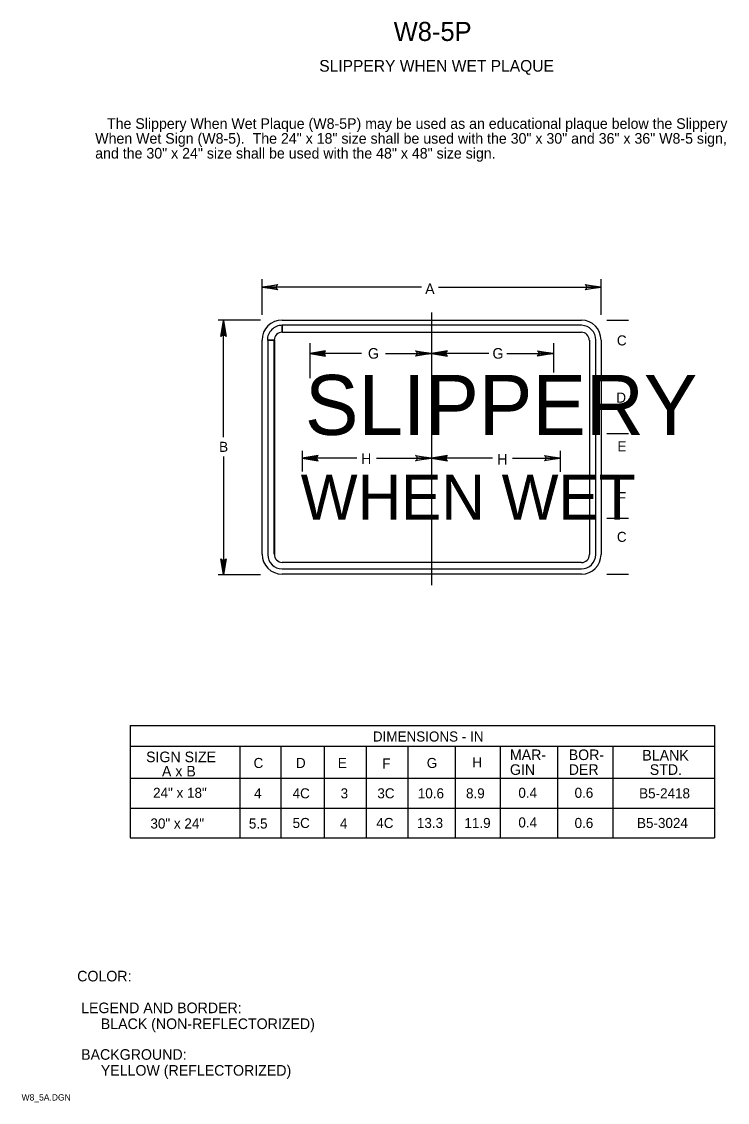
# Model space of a CAD drawing. Extents: x 0.012 to 0.179, y 0.004 to 0.259.
import ezdxf

# ---------------------------------------------------------------- set-up
doc = ezdxf.new("R2010")
doc.units = 0
for name, color, linetype in [('1', 7, 'Continuous'), ('12', 7, 'Continuous'), ('2', 7, 'Continuous'), ('3', 7, 'Continuous')]:
    doc.layers.add(name, color=color, linetype=linetype)

# ---------------------------------------------------------------- blocks, each defined once
blk = doc.blocks.new('RARROW')
at = {"layer": '3'}
for p, q in [((-2.156, 0.28500000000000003), (-2.2665, 0.384625)), ((-2.2665, 0.384625), (0, 0)), ((0, 0), (-2.2665, -0.379125)), ((-2.156, 0.28500000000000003), (-2.075625, 0.12075)), ((0, 0), (-2.156, 0.28500000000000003)), ((-2.14975, -0.2705), (0, 0)), ((-2.075625, 0.12075), (0, 0)), ((0, 0), (-2.074, -0.108)), ((-2.2665, -0.379125), (-2.14975, -0.2705)), ((-2.074, -0.108), (-2.14975, -0.2705))]:
    blk.add_line(p, q, dxfattribs=at)

msp = doc.modelspace()

# ---------------------------------------------------------------- linework, layer by layer
at = {"layer": '3'}
for p, q in [((0.069125, 0.18987500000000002), (0.069125, 0.19825)), ((0.149125, 0.18987500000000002), (0.149125, 0.19825)), ((0.10675, 0.196375), (0.069125, 0.196375)), ((0.11075, 0.196375), (0.149125, 0.196375)), ((0.109125, 0.19037500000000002), (0.109125, 0.126)), ((0.06875, 0.18862500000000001), (0.058750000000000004, 0.18862500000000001)), ((0.06, 0.161), (0.06, 0.18862500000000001)), ((0.073875, 0.18862500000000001), (0.1445, 0.18862500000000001)), ((0.1445, 0.187375), (0.073875, 0.187375)), ((0.073875, 0.187375), (0.07387569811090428, 0.18574738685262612)), ((0.07387569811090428, 0.18574738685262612), (0.073875, 0.187375)), ((0.1505, 0.18862500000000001), (0.155625, 0.18862500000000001)), ((0.069125, 0.133375), (0.069125, 0.183875)), ((0.07037500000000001, 0.183875), (0.07201621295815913, 0.18388790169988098)), ((0.07200000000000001, 0.183875), (0.07044815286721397, 0.18388790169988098)), ((0.07050000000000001, 0.183875), (0.07050000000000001, 0.13325)), ((0.07200000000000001, 0.133375), (0.07200000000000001, 0.183875)), ((0.07200000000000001, 0.133375), (0.07200000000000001, 0.183875)), ((0.0720351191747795, 0.18384855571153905), (0.0720351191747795, 0.13334855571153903)), ((0.0720351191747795, 0.13334855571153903), (0.0720351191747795, 0.18384855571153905)), ((0.0720351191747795, 0.18384855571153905), (0.0720351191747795, 0.13334855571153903)), ((0.073875, 0.18575), (0.1445, 0.18575)), ((0.146375, 0.183875), (0.146375, 0.13325)), ((0.147875, 0.13325), (0.147875, 0.183875)), ((0.149125, 0.183875), (0.149125, 0.13325)), ((0.080375, 0.183125), (0.080375, 0.174875)), ((0.137875, 0.183125), (0.137875, 0.17625)), ((0.092625, 0.18075), (0.080375, 0.18075)), ((0.09825, 0.18075), (0.109125, 0.18075)), ((0.122625, 0.18075), (0.109125, 0.18075)), ((0.12687500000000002, 0.18075), (0.137875, 0.18075)), ((0.1505, 0.17525000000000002), (0.155625, 0.17525000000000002)), ((0.1505, 0.161875), (0.155625, 0.161875)), ((0.06, 0.15637500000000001), (0.06, 0.128625)), ((0.078625, 0.15775), (0.078625, 0.152875)), ((0.0915, 0.156), (0.078625, 0.156)), ((0.096125, 0.156), (0.109125, 0.156)), ((0.1235, 0.156), (0.109125, 0.156)), ((0.12825, 0.156), (0.1395, 0.156)), ((0.1395, 0.15775), (0.1395, 0.15275)), ((0.1505, 0.151875), (0.155625, 0.151875)), ((0.1505, 0.141875), (0.155625, 0.141875)), ((0.1445, 0.131375), (0.073875, 0.131375)), ((0.06875, 0.1285), (0.058750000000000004, 0.1285)), ((0.073875, 0.129875), (0.1445, 0.129875)), ((0.1445, 0.128625), (0.073875, 0.128625)), ((0.1505, 0.128625), (0.155625, 0.128625)), ((0.038, 0.092875), (0.175875, 0.092875)), ((0.038039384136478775, 0.09287569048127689), (0.038039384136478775, 0.0663756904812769)), ((0.17593791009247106, 0.09287569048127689), (0.17593791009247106, 0.0663756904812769)), ((0.038, 0.088), (0.175875, 0.088)), ((0.06387418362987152, 0.08802738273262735), (0.06387418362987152, 0.0663756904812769)), ((0.07353938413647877, 0.08800069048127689), (0.07353938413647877, 0.0663756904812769)), ((0.08375655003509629, 0.08800069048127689), (0.08375655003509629, 0.0663756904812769)), ((0.09368984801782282, 0.08800069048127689), (0.09368984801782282, 0.0663756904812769)), ((0.10356484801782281, 0.08800069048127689), (0.10356484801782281, 0.0663756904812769)), ((0.11468984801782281, 0.08800069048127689), (0.11468984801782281, 0.0663756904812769)), ((0.1253620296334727, 0.08802738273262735), (0.1253620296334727, 0.0663756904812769)), ((0.13882622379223, 0.08802738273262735), (0.13882622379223, 0.0663756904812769)), ((0.1519163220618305, 0.08802738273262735), (0.1519163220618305, 0.0663756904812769)), ((0.038, 0.0805), (0.175875, 0.0805)), ((0.038, 0.073375), (0.175875, 0.073375)), ((0.038, 0.066375), (0.175875, 0.066375))]:
    msp.add_line(p, q, dxfattribs=at)
for centre, radius, start, end in [((0.07387500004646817, 0.1838749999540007), 0.004750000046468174, 90, 180), ((0.07387499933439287, 0.18387500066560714), 0.003499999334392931, 89.9999888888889, 180.00001111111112), ((0.14443750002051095, 0.18393750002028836), 0.004687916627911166, 359.2361, 89.23610000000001), ((0.14443749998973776, 0.18393749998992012), 0.003438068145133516, 358.95837222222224, 88.95837222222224), ((0.07387569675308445, 0.1838879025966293), 0.0018594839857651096, 90, 180), ((0.1444956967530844, 0.1838879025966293), 0.0018594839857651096, 0, 90), ((0.07387499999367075, 0.13337499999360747), 0.004749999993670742, 180, 270), ((0.07387500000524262, 0.13325000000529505), 0.003375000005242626, 180, 270), ((0.07392547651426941, 0.13329877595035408), 0.001891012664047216, 178.49155000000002, 268.49155), ((0.14450000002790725, 0.13324999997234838), 0.004624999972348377, 270, 0), ((0.1444999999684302, 0.1332500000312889), 0.0033750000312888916, 270, 0), ((0.14449999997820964, 0.1332500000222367), 0.0018750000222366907, 270, 0)]:
    msp.add_arc(centre, radius, start, end, dxfattribs=at)

# ---------------------------------------------------------------- block references
at = {"layer": '3', "xscale": 0.0016545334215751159}
for p, yscale, rotation in [((0.069125, 0.196375), 0.0016366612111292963, 180), ((0.06, 0.1885), 0.0016366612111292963, 90), ((0.080375, 0.18075), -0.0016366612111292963, -180), ((0.109125, 0.18075), -0.0016366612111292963, -180), ((0.078625, 0.156), -0.0016366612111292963, -180), ((0.109125, 0.156), -0.0016366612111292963, -180), ((0.06, 0.1285), 0.0016366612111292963, -90)]:
    msp.add_blockref('RARROW', p, dxfattribs=dict(at, yscale=yscale, rotation=rotation))
at = {"layer": '3', "xscale": 0.0016545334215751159, "yscale": 0.0016366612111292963}
for p in [(0.149125, 0.196375), (0.109125, 0.18075), (0.137875, 0.18075), (0.109125, 0.156), (0.1395, 0.156)]:
    msp.add_blockref('RARROW', p, dxfattribs=at)

# ---------------------------------------------------------------- texts
at = {"layer": '1'}
for s, height, p in [('W8-5P', 0.0045000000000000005, (0.10019590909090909, 0.2545)), ('SLIPPERY WHEN WET PLAQUE', 0.00275025, (0.082625, 0.24725)), ('COLOR:', 0.0024997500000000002, (0.025500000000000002, 0.0325)), (' LEGEND AND BORDER:', 0.0024997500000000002, (0.025500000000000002, 0.025)), ('      BLACK (NON-REFLECTORIZED)', 0.0024997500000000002, (0.025500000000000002, 0.02125)), (' BACKGROUND:', 0.0024997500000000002, (0.025500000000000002, 0.014)), ('      YELLOW (REFLECTORIZED)', 0.0024997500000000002, (0.025500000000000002, 0.01025)), ('W8_5A.DGN', 0.0015, (0.012375, 0.004375))]:
    msp.add_text(s, height=height, dxfattribs=at).set_placement(p)
at = {"layer": '12'}
for s, height, p in [('SLIPPERY', 0.01416, (0.07925, 0.1615)), ('WHEN WET', 0.01064025, (0.07825, 0.14150000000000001))]:
    msp.add_text(s, height=height, dxfattribs=at).set_placement(p)
at = {"layer": '2'}
for s, p in [('   The Slippery When Wet Plaque (W8-5P) may be used as an educational plaque below the Slippery ', (0.029750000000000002, 0.233749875)), ('When Wet Sign (W8-5).  The 24" x 18" size shall be used with the 30" x 30" and 36" x 36" W8-5 sign, ', (0.029750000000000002, 0.230250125)), ('and the 30" x 24" size shall be used with the 48" x 48" size sign.', (0.029750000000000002, 0.226750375))]:
    msp.add_text(s, height=0.0024997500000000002, dxfattribs=at).set_placement(p)
at = {"layer": '3'}
for s, height, p in [('A', 0.0024997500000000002, (0.107625, 0.19475)), ('C', 0.0023752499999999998, (0.152875, 0.182625)), ('G', 0.0024997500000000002, (0.094125, 0.1795)), ('G', 0.0024997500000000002, (0.1235, 0.1795)), ('D', 0.0023752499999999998, (0.15275, 0.169125)), ('B', 0.0023752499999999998, (0.059000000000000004, 0.1575)), ('E', 0.0023752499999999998, (0.153, 0.15762500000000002)), ('H', 0.0024997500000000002, (0.0925, 0.154625)), ('H', 0.0024997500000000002, (0.124625, 0.1545)), ('F', 0.0024997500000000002, (0.153, 0.1455)), ('C', 0.0023752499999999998, (0.152875, 0.13625)), ('DIMENSIONS - IN', 0.0023752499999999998, (0.09527678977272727, 0.089125)), ('SIGN SIZE', 0.0024997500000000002, (0.04175, 0.08425)), ('MAR-', 0.0024997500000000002, (0.12762500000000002, 0.08475)), ('BOR-', 0.0024997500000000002, (0.14150000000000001, 0.08475)), ('BLANK', 0.0024997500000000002, (0.15887500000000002, 0.084625)), ('C', 0.0023752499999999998, (0.067125, 0.082875)), ('D', 0.0023752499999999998, (0.077125, 0.082875)), ('E', 0.0023752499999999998, (0.08700000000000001, 0.082875)), ('F', 0.0023752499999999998, (0.0975, 0.08275)), ('G', 0.0023752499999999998, (0.108, 0.082875)), ('H', 0.0023752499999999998, (0.11875000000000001, 0.083)), ('A x B', 0.0024997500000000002, (0.0455, 0.080875)), ('GIN', 0.0024997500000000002, (0.12762500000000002, 0.08125)), ('DER', 0.0024997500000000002, (0.14150000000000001, 0.08125)), ('STD.', 0.0024997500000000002, (0.160625, 0.08125)), ('24" x 18"', 0.0023752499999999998, (0.04340823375, 0.07583573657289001)), ('4', 0.0023752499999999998, (0.06724652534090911, 0.07571073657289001)), ('4C', 0.0023752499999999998, (0.07633985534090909, 0.07571073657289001)), ('3', 0.0023752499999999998, (0.08766759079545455, 0.07571073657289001)), ('3C', 0.0023752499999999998, (0.09633985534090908, 0.07571073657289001)), ('10.6', 0.0023752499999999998, (0.10588304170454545, 0.07571073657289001)), ('8.9', 0.0023752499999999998, (0.11726164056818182, 0.07571073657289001)), ('0.4', 0.0023752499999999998, (0.1296215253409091, 0.07583573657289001)), ('0.6', 0.0023752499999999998, (0.14288304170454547, 0.07583573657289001)), ('B5-2418', 0.0023752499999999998, (0.15812008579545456, 0.07571073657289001)), ('30" x 24"', 0.0023752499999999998, (0.04278323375, 0.06858573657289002)), ('5.5', 0.0023752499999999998, (0.06601092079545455, 0.06858573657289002)), ('5C', 0.0023752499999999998, (0.07633985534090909, 0.06871073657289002)), ('4', 0.0023752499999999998, (0.0874965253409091, 0.06858573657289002)), ('4C', 0.0023752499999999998, (0.09608985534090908, 0.06871073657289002)), ('13.3', 0.0023752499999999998, (0.10566759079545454, 0.06871073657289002)), ('11.9', 0.0023752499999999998, (0.11688664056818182, 0.06871073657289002)), ('0.4', 0.0023752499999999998, (0.1296215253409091, 0.06883573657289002)), ('0.6', 0.0023752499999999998, (0.14288304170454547, 0.06871073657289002)), ('B5-3024', 0.0023752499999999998, (0.15762152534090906, 0.06871073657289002))]:
    msp.add_text(s, height=height, dxfattribs=at).set_placement(p)

doc.saveas('drawing.dxf')
